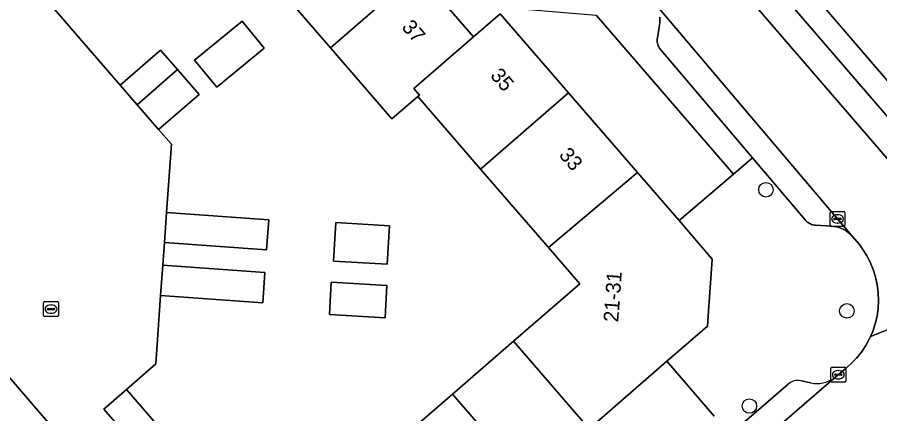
# Model space of a CAD drawing. Extents: x 160304 to 160955, y 383684 to 384161.
# Drawn here: x 160416.5 to 160474.6, y 384029 to 384055.7 of the extents above; entities that cross this region are included whole.
import ezdxf

# ---------------------------------------------------------------- set-up
doc = ezdxf.new("R2010")
doc.units = 0
for name, color, linetype in [('IMGEO_Boom', 7, 'Continuous'), ('IMGEO_Erf', 7, 'Continuous'), ('IMGEO_Kolk', 7, 'Continuous'), ('IMGEO_Pand', 7, 'Continuous'), ('IMGEO_Pand_nummerreeks', 7, 'Continuous'), ('IMGEO_Parkeervlak_open', 7, 'Continuous'), ('IMGEO_Rijbaan_lokaal_open', 7, 'Continuous'), ('IMGEO_Voetpad_open', 7, 'Continuous')]:
    doc.layers.add(name, color=color, linetype=linetype)

msp = doc.modelspace()

# ---------------------------------------------------------------- linework, layer by layer
at = {"layer": 'IMGEO_Boom'}
for centre in [(160466.936, 384044.071), (160472.386, 384035.922), (160465.821, 384029.525)]:
    msp.add_circle(centre, 0.489, dxfattribs=at)
at = {"layer": 'IMGEO_Erf'}
for points in [[(160431.035, 384077.833), (160428.673, 384075.798), (160432.433, 384071.455), (160436.115, 384067.202), (160439.796, 384062.95), (160443.478, 384058.697), (160447.238, 384054.354), (160449.036, 384055.91), (160453.642, 384050.589), (160458.283, 384045.229), (160461.083, 384041.994), (160464.755, 384045.129), (160455.536, 384055.791), (160449.608, 384056.274)], [(160429.965, 384050.959), (160428.465, 384052.779), (160431.665, 384055.417), (160433.165, 384053.597)], [(160441.59, 384041.655), (160441.434, 384039.062), (160437.824, 384039.278), (160437.979, 384041.871)], [(160441.417, 384037.633), (160441.291, 384035.454), (160437.55, 384035.67), (160437.676, 384037.849)]]:
    msp.add_lwpolyline(points, close=True, dxfattribs=at)
for points in [[(160464.114, 384064.194), (160482.27, 384043.068)], [(160441.483, 384026.556), (160445.837, 384030.325), (160449.944, 384033.881), (160454.4, 384037.739), (160452.287, 384040.18), (160447.717, 384045.459), (160443.491, 384050.34), (160441.756, 384048.838), (160437.615, 384053.621), (160433.934, 384057.873)], [(160418.58, 384056.734), (160423.46, 384051.105), (160426.181, 384053.464), (160427.323, 384052.147), (160428.769, 384050.479), (160426.048, 384048.12), (160426.908, 384047.127), (160426.58, 384042.539), (160433.463, 384042.047), (160433.319, 384040.022), (160426.436, 384040.514), (160426.327, 384038.988), (160433.21, 384038.496), (160433.064, 384036.461), (160426.181, 384036.953), (160425.853, 384032.37), (160423.895, 384030.632), (160426.46, 384027.667)], [(160415.887, 383989.594), (160418.503, 383989.954), (160429.993, 384000), (160434.935, 384004.073), (160433.617, 384005.604), (160436.338, 384007.945), (160429.882, 384015.395), (160427.166, 384013.044), (160425.937, 384014.464), (160424.585, 384016.025), (160427.301, 384018.376), (160422.435, 384023.998), (160419.719, 384021.647), (160418.52, 384023.031), (160417.138, 384024.628), (160419.854, 384026.979), (160415.02, 384032.564)], [(160463.456, 384028.84), (160460.261, 384032.534), (160455.025, 384028.001)]]:
    msp.add_lwpolyline(points, dxfattribs=at)
at = {"layer": 'IMGEO_Kolk'}
for p, q in [((160471.256, 384041.683), (160471.256, 384042.535)), ((160471.331, 384042.609), (160472.183, 384042.609)), ((160471.558, 384042.152), (160471.956, 384042.152)), ((160471.744, 384042.389), (160471.769, 384042.389)), ((160472.257, 384042.535), (160472.257, 384041.683)), ((160472.183, 384041.609), (160471.331, 384041.609)), ((160471.515, 384042.103), (160471.515, 384042.115)), ((160471.953, 384042.066), (160471.555, 384042.066)), ((160471.767, 384041.829), (160471.742, 384041.829)), ((160471.999, 384042.115), (160471.999, 384042.103)), ((160418.306, 384035.619), (160418.306, 384036.471)), ((160418.381, 384036.545), (160419.233, 384036.545)), ((160418.794, 384036.325), (160418.819, 384036.325)), ((160419.307, 384036.471), (160419.307, 384035.619)), ((160418.565, 384036.039), (160418.565, 384036.051)), ((160419.003, 384036.002), (160418.605, 384036.002)), ((160418.608, 384036.088), (160419.006, 384036.088)), ((160418.817, 384035.765), (160418.792, 384035.765)), ((160419.049, 384036.051), (160419.049, 384036.039)), ((160419.233, 384035.545), (160418.381, 384035.545)), ((160471.309, 384031.207), (160471.309, 384032.059)), ((160471.384, 384032.133), (160472.236, 384032.133)), ((160471.611, 384031.676), (160472.009, 384031.676)), ((160471.797, 384031.913), (160471.822, 384031.913)), ((160472.31, 384032.059), (160472.31, 384031.207)), ((160472.236, 384031.133), (160471.384, 384031.133)), ((160471.568, 384031.627), (160471.568, 384031.639)), ((160472.006, 384031.59), (160471.608, 384031.59)), ((160471.82, 384031.353), (160471.795, 384031.353)), ((160472.052, 384031.639), (160472.052, 384031.627))]:
    msp.add_line(p, q, dxfattribs=at)
for points in [[(160471.256, 384041.683), (160471.256, 384042.535)], [(160471.331, 384042.609), (160472.183, 384042.609)], [(160472.257, 384042.535), (160472.257, 384041.683)], [(160472.183, 384041.609), (160471.331, 384041.609)], [(160418.306, 384035.619), (160418.306, 384036.471)], [(160418.381, 384036.545), (160419.233, 384036.545)], [(160419.307, 384036.471), (160419.307, 384035.619)], [(160419.233, 384035.545), (160418.381, 384035.545)], [(160471.309, 384031.207), (160471.309, 384032.059)], [(160471.384, 384032.133), (160472.236, 384032.133)], [(160472.31, 384032.059), (160472.31, 384031.207)], [(160472.236, 384031.133), (160471.384, 384031.133)]]:
    msp.add_lwpolyline(points, dxfattribs=at)
for centre, radius, start, end in [((160471.333, 384042.533), 0.0765, 91.55205, 178.44795), ((160471.333, 384042.533), 0.0765, 91.55205, 178.44795), ((160471.555, 384042.112), 0.0403, 85.87752, 175.75265), ((160471.96, 384042.114), 0.0386, 1.73085, 96.63898), ((160472.181, 384042.533), 0.0765, 1.55205, 88.44795), ((160472.181, 384042.533), 0.0765, 1.55205, 88.44795), ((160471.333, 384041.685), 0.0765, 181.55205, 268.44795), ((160471.333, 384041.685), 0.0765, 181.55205, 268.44795), ((160471.552, 384042.102), 0.0366, 178.93798, 274.71019), ((160471.956, 384042.109), 0.043, 264.86636, 352.45326), ((160472.181, 384041.685), 0.0765, 271.55205, 358.44795), ((160472.181, 384041.685), 0.0765, 271.55205, 358.44795), ((160418.383, 384036.469), 0.0765, 91.55205, 178.44795), ((160418.383, 384036.469), 0.0765, 91.55205, 178.44795), ((160419.231, 384036.469), 0.0765, 1.55205, 88.44795), ((160419.231, 384036.469), 0.0765, 1.55205, 88.44795), ((160418.605, 384036.048), 0.0403, 85.87752, 175.75265), ((160418.602, 384036.038), 0.0366, 178.93798, 274.71019), ((160419.006, 384036.045), 0.043, 264.86636, 352.45326), ((160419.01, 384036.05), 0.0386, 1.73085, 96.63898), ((160418.383, 384035.621), 0.0765, 181.55205, 268.44795), ((160418.383, 384035.621), 0.0765, 181.55205, 268.44795), ((160419.231, 384035.621), 0.0765, 271.55205, 358.44795), ((160419.231, 384035.621), 0.0765, 271.55205, 358.44795), ((160471.386, 384032.057), 0.0765, 91.55205, 178.44795), ((160471.386, 384032.057), 0.0765, 91.55205, 178.44795), ((160471.608, 384031.636), 0.0403, 85.87752, 175.75265), ((160472.013, 384031.638), 0.0386, 1.73085, 96.63898), ((160472.234, 384032.057), 0.0765, 1.55205, 88.44795), ((160472.234, 384032.057), 0.0765, 1.55205, 88.44795), ((160471.386, 384031.209), 0.0765, 181.55205, 268.44795), ((160471.386, 384031.209), 0.0765, 181.55205, 268.44795), ((160471.605, 384031.626), 0.0366, 178.93798, 274.71019), ((160472.009, 384031.633), 0.043, 264.86636, 352.45326), ((160472.234, 384031.209), 0.0765, 271.55205, 358.44795), ((160472.234, 384031.209), 0.0765, 271.55205, 358.44795)]:
    msp.add_arc(centre, radius, start, end, dxfattribs=at)
for centre, major_axis, ratio, start_param, end_param in [((160471.743, 384042.109), (-0.387, 0.002), 0.722429, 4.712389, 7.853982), ((160471.768, 384042.109), (-0.39, 0.002), 0.717154, 1.570796, 4.712389), ((160418.793, 384036.045), (-0.387, 0.002), 0.722429, 4.712389, 7.853982), ((160418.818, 384036.045), (-0.39, 0.002), 0.717154, 1.570796, 4.712389), ((160471.796, 384031.633), (-0.387, 0.002), 0.722429, 4.712389, 7.853982), ((160471.821, 384031.633), (-0.39, 0.002), 0.717154, 1.570796, 4.712389)]:
    msp.add_ellipse(centre, major_axis=major_axis, ratio=ratio, start_param=start_param, end_param=end_param, dxfattribs=at)
at = {"layer": 'IMGEO_Pand'}
for points in [[(160437.615, 384053.621), (160443.478, 384058.697), (160439.796, 384062.95), (160433.934, 384057.873)], [(160447.238, 384054.354), (160443.478, 384058.697), (160437.615, 384053.621), (160441.756, 384048.838), (160443.491, 384050.34), (160443.602, 384050.436), (160443.223, 384050.875)], [(160447.717, 384045.459), (160453.642, 384050.589), (160449.036, 384055.91), (160447.238, 384054.354), (160443.223, 384050.875), (160443.602, 384050.436), (160443.491, 384050.34)], [(160431.665, 384055.417), (160428.465, 384052.779), (160429.965, 384050.959), (160433.165, 384053.597)], [(160424.601, 384049.789), (160427.323, 384052.147), (160426.181, 384053.464), (160423.46, 384051.105)], [(160424.601, 384049.789), (160426.048, 384048.12), (160428.769, 384050.479), (160427.323, 384052.147)], [(160447.717, 384045.459), (160452.287, 384040.18), (160458.283, 384045.229), (160453.642, 384050.589)], [(160463.097, 384036.252), (160463.23, 384038.097), (160463.324, 384039.406), (160461.083, 384041.994), (160458.283, 384045.229), (160452.287, 384040.18), (160454.4, 384037.739), (160449.944, 384033.881), (160455.025, 384028.001), (160460.261, 384032.534), (160463, 384034.905)], [(160426.436, 384040.514), (160433.319, 384040.022), (160433.463, 384042.047), (160426.58, 384042.539)], [(160441.59, 384041.655), (160437.979, 384041.871), (160437.824, 384039.278), (160441.434, 384039.062)], [(160426.327, 384038.988), (160426.181, 384036.953), (160433.064, 384036.461), (160433.21, 384038.496)], [(160441.417, 384037.633), (160437.676, 384037.849), (160437.55, 384035.67), (160441.291, 384035.454)], [(160445.837, 384030.325), (160450.924, 384024.45), (160455.025, 384028.001), (160449.944, 384033.881)], [(160423.895, 384030.632), (160422.367, 384029.31), (160424.932, 384026.345), (160426.46, 384027.667)], [(160445.837, 384030.325), (160441.483, 384026.556), (160446.57, 384020.681), (160450.924, 384024.45)]]:
    msp.add_lwpolyline(points, close=True, dxfattribs=at)
at = {"layer": 'IMGEO_Parkeervlak_open'}
for points in [[(160462.073, 384061.277), (160462.515, 384060.763), (160477.506, 384043.391)], [(160477.007, 384046.807), (160465.495, 384060.157)], [(160459.781, 384055.68), (160459.793, 384055.501), (160459.788, 384055.321), (160459.768, 384055.142), (160459.629, 384054.284), (160459.619, 384054.195), (160459.616, 384054.106), (160459.622, 384054.016), (160459.636, 384053.928), (160459.657, 384053.841), (160459.687, 384053.756), (160459.723, 384053.674), (160459.767, 384053.596), (160459.818, 384053.522), (160459.854, 384053.477), (160466.027, 384046.209), (160469.569, 384042.039), (160469.63, 384041.973), (160469.698, 384041.913), (160469.77, 384041.859), (160469.846, 384041.812), (160469.927, 384041.772), (160470.011, 384041.739), (160470.097, 384041.714), (160470.186, 384041.697), (160470.272, 384041.688), (160471.36, 384041.624), (160471.504, 384041.61), (160471.68, 384041.579), (160471.853, 384041.533), (160472.02, 384041.471), (160472.182, 384041.394), (160472.336, 384041.303), (160472.481, 384041.199), (160472.617, 384041.082), (160472.741, 384040.954), (160459.355, 384056.713)], [(160443.247, 384006.975), (160471.504, 384031.385)], [(160469.964, 384031.082), (160469.297, 384031.223)], [(160468.436, 384031.002), (160444.182, 384010.054)]]:
    msp.add_lwpolyline(points, dxfattribs=at)
for centre, radius, start, end in [((160469.088, 384030.251), 0.994, 77.83567, 130.95594), ((160470.382, 384033.025), 1.987, 257.87289, 304.38901)]:
    msp.add_arc(centre, radius, start, end, dxfattribs=at)
at = {"layer": 'IMGEO_Rijbaan_lokaal_open'}
for points in [[(160479.834, 384040.678), (160479.686, 384040.851), (160477.506, 384043.391), (160462.515, 384060.763), (160462.073, 384061.277)], [(160415.02, 384032.564), (160419.854, 384026.979), (160421.238, 384025.38), (160422.435, 384023.998), (160427.301, 384018.376), (160428.654, 384016.814), (160429.882, 384015.395), (160436.338, 384007.945), (160437.655, 384006.413), (160440.174, 384008.722), (160424.932, 384026.345), (160422.367, 384029.31), (160423.895, 384030.632), (160425.853, 384032.37), (160426.181, 384036.953), (160426.327, 384038.988), (160426.436, 384040.514), (160426.58, 384042.539), (160426.908, 384047.127), (160426.048, 384048.12), (160424.601, 384049.789), (160423.46, 384051.105), (160418.58, 384056.734)], [(160459.355, 384056.713), (160472.741, 384040.954), (160473.226, 384040.382), (160473.425, 384040.118), (160473.712, 384039.671), (160473.959, 384039.2), (160474.162, 384038.71), (160474.321, 384038.203), (160474.434, 384037.684), (160474.5, 384037.156), (160474.519, 384036.625), (160474.49, 384036.095), (160474.414, 384035.569), (160474.291, 384035.052), (160474.123, 384034.548), (160473.972, 384034.203), (160484.061, 384038.186)], [(160484.061, 384038.186), (160473.972, 384034.203), (160473.91, 384034.061), (160473.654, 384033.596), (160473.358, 384033.154), (160473.024, 384032.741), (160472.654, 384032.36), (160472.252, 384032.013), (160471.504, 384031.385), (160443.247, 384006.975), (160442.642, 384006.44), (160439.545, 384003.767), (160435.187, 384000), (160424.255, 383990.462), (160420.449, 383987.142), (160422.038, 383985.305), (160423.775, 383983.297), (160425.096, 383984.442), (160439.728, 383997.125), (160440.231, 383997.562), (160443.044, 384000), (160446.077, 384002.618), (160446.417, 384002.912), (160475.034, 384027.614)]]:
    msp.add_lwpolyline(points, dxfattribs=at)
at = {"layer": 'IMGEO_Voetpad_open'}
for points in [[(160477.506, 384043.391), (160479.686, 384040.851), (160482.27, 384043.068), (160464.114, 384064.194), (160464.179, 384070.303), (160445.759, 384091.611)], [(160465.495, 384060.157), (160477.007, 384046.807)], [(160455.536, 384055.791), (160464.755, 384045.129), (160466.027, 384046.209), (160459.854, 384053.477), (160459.818, 384053.522), (160459.767, 384053.596), (160459.723, 384053.674), (160459.687, 384053.756), (160459.657, 384053.841), (160459.636, 384053.928), (160459.622, 384054.016), (160459.616, 384054.106), (160459.619, 384054.195), (160459.629, 384054.284), (160459.768, 384055.142), (160459.788, 384055.321), (160459.793, 384055.501), (160459.781, 384055.68)], [(160471.504, 384031.385), (160472.252, 384032.013), (160472.654, 384032.36), (160473.024, 384032.741), (160473.358, 384033.154), (160473.654, 384033.596), (160473.91, 384034.061), (160473.972, 384034.203), (160474.123, 384034.548), (160474.291, 384035.052), (160474.414, 384035.569), (160474.49, 384036.095), (160474.519, 384036.625), (160474.5, 384037.156), (160474.434, 384037.684), (160474.321, 384038.203), (160474.162, 384038.71), (160473.959, 384039.2), (160473.712, 384039.671), (160473.425, 384040.118), (160473.226, 384040.382), (160472.741, 384040.954), (160472.617, 384041.082), (160472.481, 384041.199), (160472.336, 384041.303), (160472.182, 384041.394), (160472.02, 384041.471), (160471.853, 384041.533), (160471.68, 384041.579), (160471.504, 384041.61), (160471.36, 384041.624), (160470.272, 384041.688), (160470.186, 384041.697), (160470.097, 384041.714), (160470.011, 384041.739), (160469.927, 384041.772), (160469.846, 384041.812), (160469.77, 384041.859), (160469.698, 384041.913), (160469.63, 384041.973), (160469.569, 384042.039), (160466.027, 384046.209), (160464.755, 384045.129), (160461.083, 384041.994), (160463.324, 384039.406), (160463.23, 384038.097), (160463.097, 384036.252), (160463, 384034.905), (160460.261, 384032.534), (160463.456, 384028.84)], [(160469.297, 384031.223), (160469.964, 384031.082)], [(160444.182, 384010.054), (160468.436, 384031.002)]]:
    msp.add_lwpolyline(points, dxfattribs=at)
for centre, radius, start, end in [((160469.088, 384030.251), 0.994, 77.83567, 130.95594), ((160470.382, 384033.025), 1.987, 257.87289, 304.38901)]:
    msp.add_arc(centre, radius, start, end, dxfattribs=at)

# ---------------------------------------------------------------- texts
at = {"layer": 'IMGEO_Pand_nummerreeks'}
for s, rotation, p in [('37', 310.88606, (160442.361, 384054.976)), ('35', 310.88606, (160448.327, 384051.718)), ('33', 310.88606, (160452.951, 384046.377)), ('21-31', 85.88064, (160456.991, 384035.141))]:
    msp.add_text(s, height=1, rotation=rotation, dxfattribs=at).set_placement(p)

doc.saveas('drawing.dxf')
